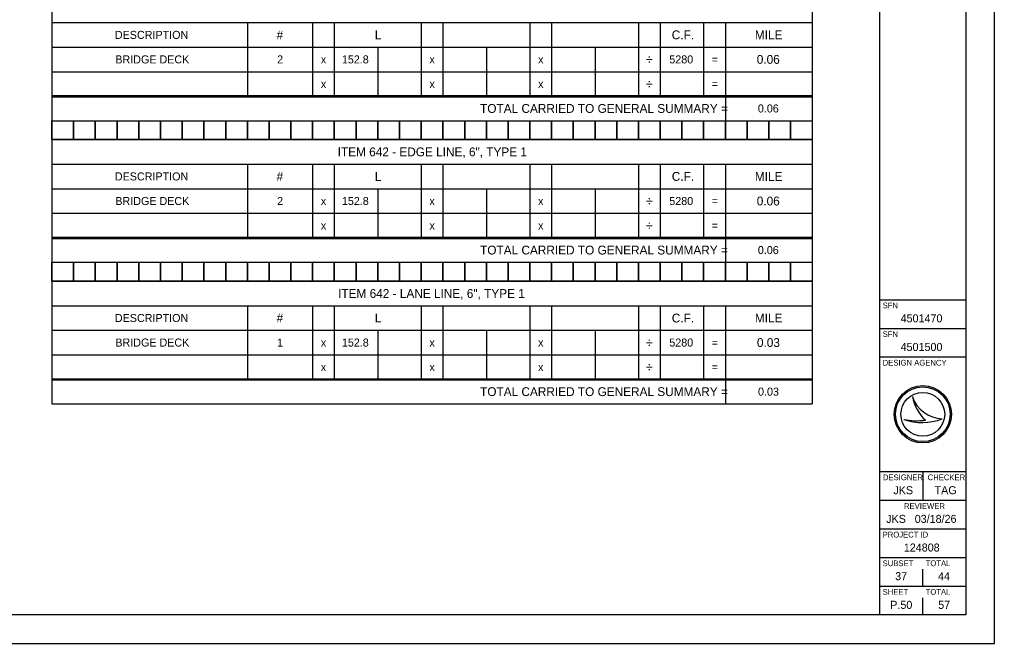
# Model space of a CAD drawing. Extents: x 0 to 34, y 0 to 22.
# Drawn here: x 17 to 34, y 0 to 10.89 of the extents above; entities that cross this region are included whole.
import ezdxf

# ---------------------------------------------------------------- set-up
doc = ezdxf.new("R2010")
doc.units = 0
for name, color, linetype in [('Default', 7, 'Continuous'), ('SH_Border', 7, 'Continuous'), ('SH_Cut_Line', 7, 'Continuous'), ('SH_Data', 7, 'Continuous')]:
    doc.layers.add(name, color=color, linetype=linetype)

msp = doc.modelspace()

# ---------------------------------------------------------------- linework, layer by layer
at = {"layer": 'Default'}
for p, q in [((17.564, 12.032), (17.564, 9.54)), ((30.823, 12.032), (30.823, 9.54)), ((17.564, 10.835), (30.823, 10.835)), ((20.974, 10.835), (20.974, 9.562)), ((22.11, 10.835), (22.11, 9.562)), ((22.489, 10.835), (22.489, 9.562)), ((24.004, 10.835), (24.004, 9.562)), ((24.383, 10.835), (24.383, 9.562)), ((25.898, 10.835), (25.898, 9.562)), ((26.277, 10.835), (26.277, 9.562)), ((27.792, 10.835), (27.792, 9.562)), ((28.171, 10.835), (28.171, 9.562)), ((28.929, 10.835), (28.929, 9.562)), ((29.308, 10.835), (29.308, 9.562)), ((17.564, 10.407), (30.823, 10.407)), ((23.247, 10.407), (23.247, 9.562)), ((25.141, 10.407), (25.141, 9.562)), ((27.035, 10.407), (27.035, 9.562)), ((17.564, 9.979), (30.823, 9.979)), ((17.564, 9.562), (30.823, 9.562)), ((17.564, 9.562), (17.564, 7.069)), ((17.564, 9.54), (30.823, 9.54)), ((29.308, 9.54), (29.308, 9.123)), ((30.823, 9.562), (30.823, 7.069)), ((17.564, 9.123), (30.823, 9.123)), ((17.564, 8.793), (30.823, 8.793)), ((17.564, 8.365), (30.823, 8.365)), ((20.974, 8.365), (20.974, 7.091)), ((22.11, 8.365), (22.11, 7.091)), ((22.489, 8.365), (22.489, 7.091)), ((24.004, 8.365), (24.004, 7.091)), ((24.383, 8.365), (24.383, 7.091)), ((25.898, 8.365), (25.898, 7.091)), ((26.277, 8.365), (26.277, 7.091)), ((27.792, 8.365), (27.792, 7.091)), ((28.171, 8.365), (28.171, 7.091)), ((28.929, 8.365), (28.929, 7.091)), ((29.308, 8.365), (29.308, 7.091)), ((17.564, 7.937), (30.823, 7.937)), ((23.247, 7.937), (23.247, 7.091)), ((25.141, 7.937), (25.141, 7.091)), ((27.035, 7.937), (27.035, 7.091)), ((17.564, 7.508), (30.823, 7.508)), ((17.564, 7.091), (30.823, 7.091)), ((17.564, 7.091), (17.564, 4.599)), ((17.564, 7.069), (30.823, 7.069)), ((29.308, 7.069), (29.308, 6.652)), ((30.823, 7.091), (30.823, 4.599)), ((17.564, 6.652), (30.823, 6.652)), ((17.564, 6.322), (30.823, 6.322)), ((17.564, 5.894), (30.823, 5.894)), ((20.974, 5.894), (20.974, 4.621)), ((22.11, 5.894), (22.11, 4.621)), ((22.489, 5.894), (22.489, 4.621)), ((24.004, 5.894), (24.004, 4.621)), ((24.383, 5.894), (24.383, 4.621)), ((25.898, 5.894), (25.898, 4.621)), ((26.277, 5.894), (26.277, 4.621)), ((27.792, 5.894), (27.792, 4.621)), ((28.171, 5.894), (28.171, 4.621)), ((28.929, 5.894), (28.929, 4.621)), ((29.308, 5.894), (29.308, 4.621)), ((17.564, 5.466), (30.823, 5.466)), ((23.247, 5.466), (23.247, 4.621)), ((25.141, 5.466), (25.141, 4.621)), ((27.035, 5.466), (27.035, 4.621)), ((17.564, 5.038), (30.823, 5.038)), ((17.564, 4.621), (30.823, 4.621)), ((17.564, 4.621), (17.564, 4.181)), ((17.564, 4.599), (30.823, 4.599)), ((29.308, 4.599), (29.308, 4.181)), ((30.823, 4.621), (30.823, 4.181)), ((17.564, 4.181), (30.823, 4.181))]:
    msp.add_line(p, q, dxfattribs=at)
for points in [[(17.564, 9.123), (17.943, 9.123), (17.943, 8.793), (17.564, 8.793)], [(17.943, 9.123), (18.322, 9.123), (18.322, 8.793), (17.943, 8.793)], [(18.322, 9.123), (18.701, 9.123), (18.701, 8.793), (18.322, 8.793)], [(18.701, 9.123), (19.08, 9.123), (19.08, 8.793), (18.701, 8.793)], [(19.08, 9.123), (19.458, 9.123), (19.458, 8.793), (19.08, 8.793)], [(19.458, 9.123), (19.837, 9.123), (19.837, 8.793), (19.458, 8.793)], [(19.837, 9.123), (20.216, 9.123), (20.216, 8.793), (19.837, 8.793)], [(20.216, 9.123), (20.595, 9.123), (20.595, 8.793), (20.216, 8.793)], [(20.595, 9.123), (20.974, 9.123), (20.974, 8.793), (20.595, 8.793)], [(20.974, 9.123), (21.352, 9.123), (21.352, 8.793), (20.974, 8.793)], [(21.352, 9.123), (21.731, 9.123), (21.731, 8.793), (21.352, 8.793)], [(21.731, 9.123), (22.11, 9.123), (22.11, 8.793), (21.731, 8.793)], [(22.11, 9.123), (22.489, 9.123), (22.489, 8.793), (22.11, 8.793)], [(22.489, 9.123), (22.868, 9.123), (22.868, 8.793), (22.489, 8.793)], [(22.868, 9.123), (23.247, 9.123), (23.247, 8.793), (22.868, 8.793)], [(23.247, 9.123), (23.625, 9.123), (23.625, 8.793), (23.247, 8.793)], [(23.625, 9.123), (24.004, 9.123), (24.004, 8.793), (23.625, 8.793)], [(24.004, 9.123), (24.383, 9.123), (24.383, 8.793), (24.004, 8.793)], [(24.383, 9.123), (24.762, 9.123), (24.762, 8.793), (24.383, 8.793)], [(24.762, 9.123), (25.141, 9.123), (25.141, 8.793), (24.762, 8.793)], [(25.141, 9.123), (25.52, 9.123), (25.52, 8.793), (25.141, 8.793)], [(25.52, 9.123), (25.898, 9.123), (25.898, 8.793), (25.52, 8.793)], [(25.898, 9.123), (26.277, 9.123), (26.277, 8.793), (25.898, 8.793)], [(26.277, 9.123), (26.656, 9.123), (26.656, 8.793), (26.277, 8.793)], [(26.656, 9.123), (27.035, 9.123), (27.035, 8.793), (26.656, 8.793)], [(27.035, 9.123), (27.414, 9.123), (27.414, 8.793), (27.035, 8.793)], [(27.414, 9.123), (27.792, 9.123), (27.792, 8.793), (27.414, 8.793)], [(27.792, 9.123), (28.171, 9.123), (28.171, 8.793), (27.792, 8.793)], [(28.171, 9.123), (28.55, 9.123), (28.55, 8.793), (28.171, 8.793)], [(28.55, 9.123), (28.929, 9.123), (28.929, 8.793), (28.55, 8.793)], [(28.929, 9.123), (29.308, 9.123), (29.308, 8.793), (28.929, 8.793)], [(29.308, 9.123), (29.687, 9.123), (29.687, 8.793), (29.308, 8.793)], [(29.687, 9.123), (30.065, 9.123), (30.065, 8.793), (29.687, 8.793)], [(30.065, 9.123), (30.444, 9.123), (30.444, 8.793), (30.065, 8.793)], [(30.444, 9.123), (30.823, 9.123), (30.823, 8.793), (30.444, 8.793)], [(17.564, 6.652), (17.943, 6.652), (17.943, 6.322), (17.564, 6.322)], [(17.943, 6.652), (18.322, 6.652), (18.322, 6.322), (17.943, 6.322)], [(18.322, 6.652), (18.701, 6.652), (18.701, 6.322), (18.322, 6.322)], [(18.701, 6.652), (19.08, 6.652), (19.08, 6.322), (18.701, 6.322)], [(19.08, 6.652), (19.458, 6.652), (19.458, 6.322), (19.08, 6.322)], [(19.458, 6.652), (19.837, 6.652), (19.837, 6.322), (19.458, 6.322)], [(19.837, 6.652), (20.216, 6.652), (20.216, 6.322), (19.837, 6.322)], [(20.216, 6.652), (20.595, 6.652), (20.595, 6.322), (20.216, 6.322)], [(20.595, 6.652), (20.974, 6.652), (20.974, 6.322), (20.595, 6.322)], [(20.974, 6.652), (21.352, 6.652), (21.352, 6.322), (20.974, 6.322)], [(21.352, 6.652), (21.731, 6.652), (21.731, 6.322), (21.352, 6.322)], [(21.731, 6.652), (22.11, 6.652), (22.11, 6.322), (21.731, 6.322)], [(22.11, 6.652), (22.489, 6.652), (22.489, 6.322), (22.11, 6.322)], [(22.489, 6.652), (22.868, 6.652), (22.868, 6.322), (22.489, 6.322)], [(22.868, 6.652), (23.247, 6.652), (23.247, 6.322), (22.868, 6.322)], [(23.247, 6.652), (23.625, 6.652), (23.625, 6.322), (23.247, 6.322)], [(23.625, 6.652), (24.004, 6.652), (24.004, 6.322), (23.625, 6.322)], [(24.004, 6.652), (24.383, 6.652), (24.383, 6.322), (24.004, 6.322)], [(24.383, 6.652), (24.762, 6.652), (24.762, 6.322), (24.383, 6.322)], [(24.762, 6.652), (25.141, 6.652), (25.141, 6.322), (24.762, 6.322)], [(25.141, 6.652), (25.52, 6.652), (25.52, 6.322), (25.141, 6.322)], [(25.52, 6.652), (25.898, 6.652), (25.898, 6.322), (25.52, 6.322)], [(25.898, 6.652), (26.277, 6.652), (26.277, 6.322), (25.898, 6.322)], [(26.277, 6.652), (26.656, 6.652), (26.656, 6.322), (26.277, 6.322)], [(26.656, 6.652), (27.035, 6.652), (27.035, 6.322), (26.656, 6.322)], [(27.035, 6.652), (27.414, 6.652), (27.414, 6.322), (27.035, 6.322)], [(27.414, 6.652), (27.792, 6.652), (27.792, 6.322), (27.414, 6.322)], [(27.792, 6.652), (28.171, 6.652), (28.171, 6.322), (27.792, 6.322)], [(28.171, 6.652), (28.55, 6.652), (28.55, 6.322), (28.171, 6.322)], [(28.55, 6.652), (28.929, 6.652), (28.929, 6.322), (28.55, 6.322)], [(28.929, 6.652), (29.308, 6.652), (29.308, 6.322), (28.929, 6.322)], [(29.308, 6.652), (29.687, 6.652), (29.687, 6.322), (29.308, 6.322)], [(29.687, 6.652), (30.065, 6.652), (30.065, 6.322), (29.687, 6.322)], [(30.065, 6.652), (30.444, 6.652), (30.444, 6.322), (30.065, 6.322)], [(30.444, 6.652), (30.823, 6.652), (30.823, 6.322), (30.444, 6.322)]]:
    msp.add_lwpolyline(points, close=True, dxfattribs=at)
at = {"layer": 'SH_Border'}
for p, q in [((32, 0.5), (32, 21.5)), ((32, 6), (33.5, 6)), ((32, 5.5), (33.5, 5.5)), ((32, 5), (33.5, 5)), ((32, 3), (33.5, 3)), ((32.75, 3), (32.75, 2.5)), ((32, 2.5), (33.5, 2.5)), ((32, 2), (33.5, 2)), ((32, 1.5), (33.5, 1.5)), ((32, 1), (33.5, 1))]:
    msp.add_line(p, q, dxfattribs=at)
msp.add_lwpolyline([(1.5, 21.5), (33.5, 21.5), (33.5, 0.5), (1.5, 0.5)], close=True, dxfattribs=at)
at = {"layer": 'SH_Cut_Line'}
msp.add_lwpolyline([(0, 0), (34, 0), (34, 22), (0, 22)], close=True, dxfattribs=at)
at = {"layer": 'SH_Data'}
for p, q in [((32.75, 5.675), (32.75, 5.675)), ((32.75, 5.175), (32.75, 5.175)), ((32.567, 4.31), (32.567, 4.31)), ((32.75, 4), (32.75, 4)), ((33.087, 3.919), (33.087, 3.919)), ((32.417, 3.91), (32.417, 3.91)), ((32.75, 1), (32.75, 1.3)), ((32.75, 0.5), (32.75, 0.8)), ((32.375, 0.675), (32.375, 0.675))]:
    msp.add_line(p, q, dxfattribs=at)
for radius in [0.5, 0.477, 0.477, 0.382]:
    msp.add_circle((32.75, 4), radius, dxfattribs=at)
for centre, radius, start, end in [((33.116, 4.498), 0.58, 198.9257, 198.9319), ((33.347, 4.47), 0.796, 191.6379, 191.6421), ((33.116, 4.498), 0.58, 198.9319, 267.1657), ((33.347, 4.47), 0.796, 191.6421, 226.0947), ((32.739, 4.87), 1.013, 251.4576, 290.0832), ((32.648, 5.154), 1.266, 259.4964, 259.4995), ((32.739, 4.87), 1.013, 251.4527, 251.4576), ((32.648, 5.154), 1.266, 259.4995, 276.6672)]:
    msp.add_arc(centre, radius, start, end, dxfattribs=at)

# ---------------------------------------------------------------- texts
at = {"layer": 'Default'}
for s, height, p in [('DESCRIPTION', 0.14, (18.663, 10.551)), ('#', 0.154, (21.483, 10.544)), ('L', 0.154, (23.196, 10.544)), ('C.F.', 0.154, (28.373, 10.544)), ('MILE', 0.154, (29.822, 10.544)), ('BRIDGE DECK', 0.14, (18.671, 10.123)), ('2', 0.14, (21.492, 10.123)), ('x', 0.14, (22.254, 10.123)), ('152.8', 0.14, (22.621, 10.123)), ('x', 0.14, (24.148, 10.123)), ('x', 0.14, (26.042, 10.123)), ('÷', 0.168, (27.92, 10.109)), ('5280', 0.14, (28.33, 10.123)), ('=', 0.14, (29.069, 10.123)), ('0.06', 0.154, (29.855, 10.116)), ('x', 0.14, (22.254, 9.695)), ('x', 0.14, (24.148, 9.695)), ('x', 0.14, (26.042, 9.695)), ('÷', 0.168, (27.92, 9.681)), ('=', 0.14, (29.069, 9.695)), ('TOTAL CARRIED TO GENERAL SUMMARY =', 0.154, (25.031, 9.26)), ('0.06', 0.14, (29.874, 9.267)), ('ITEM 642 - EDGE LINE, 6", TYPE 1', 0.154, (22.548, 8.502)), ('DESCRIPTION', 0.14, (18.663, 8.081)), ('#', 0.154, (21.483, 8.074)), ('L', 0.154, (23.196, 8.074)), ('C.F.', 0.154, (28.373, 8.074)), ('MILE', 0.154, (29.822, 8.074)), ('BRIDGE DECK', 0.14, (18.671, 7.652)), ('2', 0.14, (21.492, 7.652)), ('x', 0.14, (22.254, 7.652)), ('152.8', 0.14, (22.621, 7.652)), ('x', 0.14, (24.148, 7.652)), ('x', 0.14, (26.042, 7.652)), ('÷', 0.168, (27.92, 7.638)), ('5280', 0.14, (28.33, 7.652)), ('=', 0.14, (29.069, 7.652)), ('0.06', 0.154, (29.855, 7.645)), ('x', 0.14, (22.254, 7.224)), ('x', 0.14, (24.148, 7.224)), ('x', 0.14, (26.042, 7.224)), ('÷', 0.168, (27.92, 7.21)), ('=', 0.14, (29.069, 7.224)), ('TOTAL CARRIED TO GENERAL SUMMARY =', 0.154, (25.031, 6.789)), ('0.06', 0.14, (29.874, 6.796)), ('ITEM 642 - LANE LINE, 6", TYPE 1', 0.154, (22.556, 6.031)), ('DESCRIPTION', 0.14, (18.663, 5.61)), ('#', 0.154, (21.483, 5.603)), ('L', 0.154, (23.196, 5.603)), ('C.F.', 0.154, (28.373, 5.603)), ('MILE', 0.154, (29.822, 5.603)), ('BRIDGE DECK', 0.14, (18.671, 5.182)), ('1', 0.14, (21.492, 5.182)), ('x', 0.14, (22.254, 5.182)), ('152.8', 0.14, (22.621, 5.182)), ('x', 0.14, (24.148, 5.182)), ('x', 0.14, (26.042, 5.182)), ('÷', 0.168, (27.92, 5.168)), ('5280', 0.14, (28.33, 5.182)), ('=', 0.14, (29.069, 5.182)), ('0.03', 0.154, (29.858, 5.175)), ('x', 0.14, (22.254, 4.754)), ('x', 0.14, (24.148, 4.754)), ('x', 0.14, (26.042, 4.754)), ('÷', 0.168, (27.92, 4.74)), ('=', 0.14, (29.069, 4.754)), ('TOTAL CARRIED TO GENERAL SUMMARY =', 0.154, (25.031, 4.318)), ('0.03', 0.14, (29.877, 4.325))]:
    msp.add_text(s, height=height, dxfattribs=at).set_placement(p)
at = {"layer": 'SH_Data'}
for s, height, p in [('SFN', 0.1, (32.05, 5.85)), ('4501470', 0.14, (32.363, 5.605)), ('SFN', 0.1, (32.05, 5.35)), ('4501500', 0.14, (32.363, 5.105)), ('DESIGN AGENCY', 0.1, (32.05, 4.85)), ('DESIGNER', 0.1, (32.054, 2.85)), ('CHECKER', 0.1, (32.835, 2.85)), ('JKS', 0.14, (32.237, 2.605)), ('TAG', 0.14, (32.955, 2.605)), ('REVIEWER', 0.1, (32.422, 2.35)), ('JKS', 0.14, (32.112, 2.105)), ('03/18/26', 0.14, (32.609, 2.105)), ('PROJECT ID', 0.1, (32.05, 1.85)), ('124808', 0.14, (32.419, 1.605)), ('SUBSET', 0.1, (32.05, 1.35)), ('TOTAL', 0.1, (32.8, 1.35)), ('37', 0.14, (32.268, 1.105)), ('44', 0.14, (33.016, 1.105)), ('SHEET', 0.1, (32.05, 0.85)), ('TOTAL', 0.1, (32.8, 0.85)), ('P.50', 0.14, (32.182, 0.605)), ('57', 0.14, (33.018, 0.605))]:
    msp.add_text(s, height=height, dxfattribs=at).set_placement(p)

doc.saveas('drawing.dxf')
